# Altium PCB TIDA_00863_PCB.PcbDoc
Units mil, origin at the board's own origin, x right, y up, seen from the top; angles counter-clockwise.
Board outline 3000 x 2000 mil, 4 copper layers (Top Layer, Signal Layer 1, Signal Layer 2, Bottom Layer), stack 61.6 mil thick; 36 components, 14 nets, 116 pads, 117 vias.
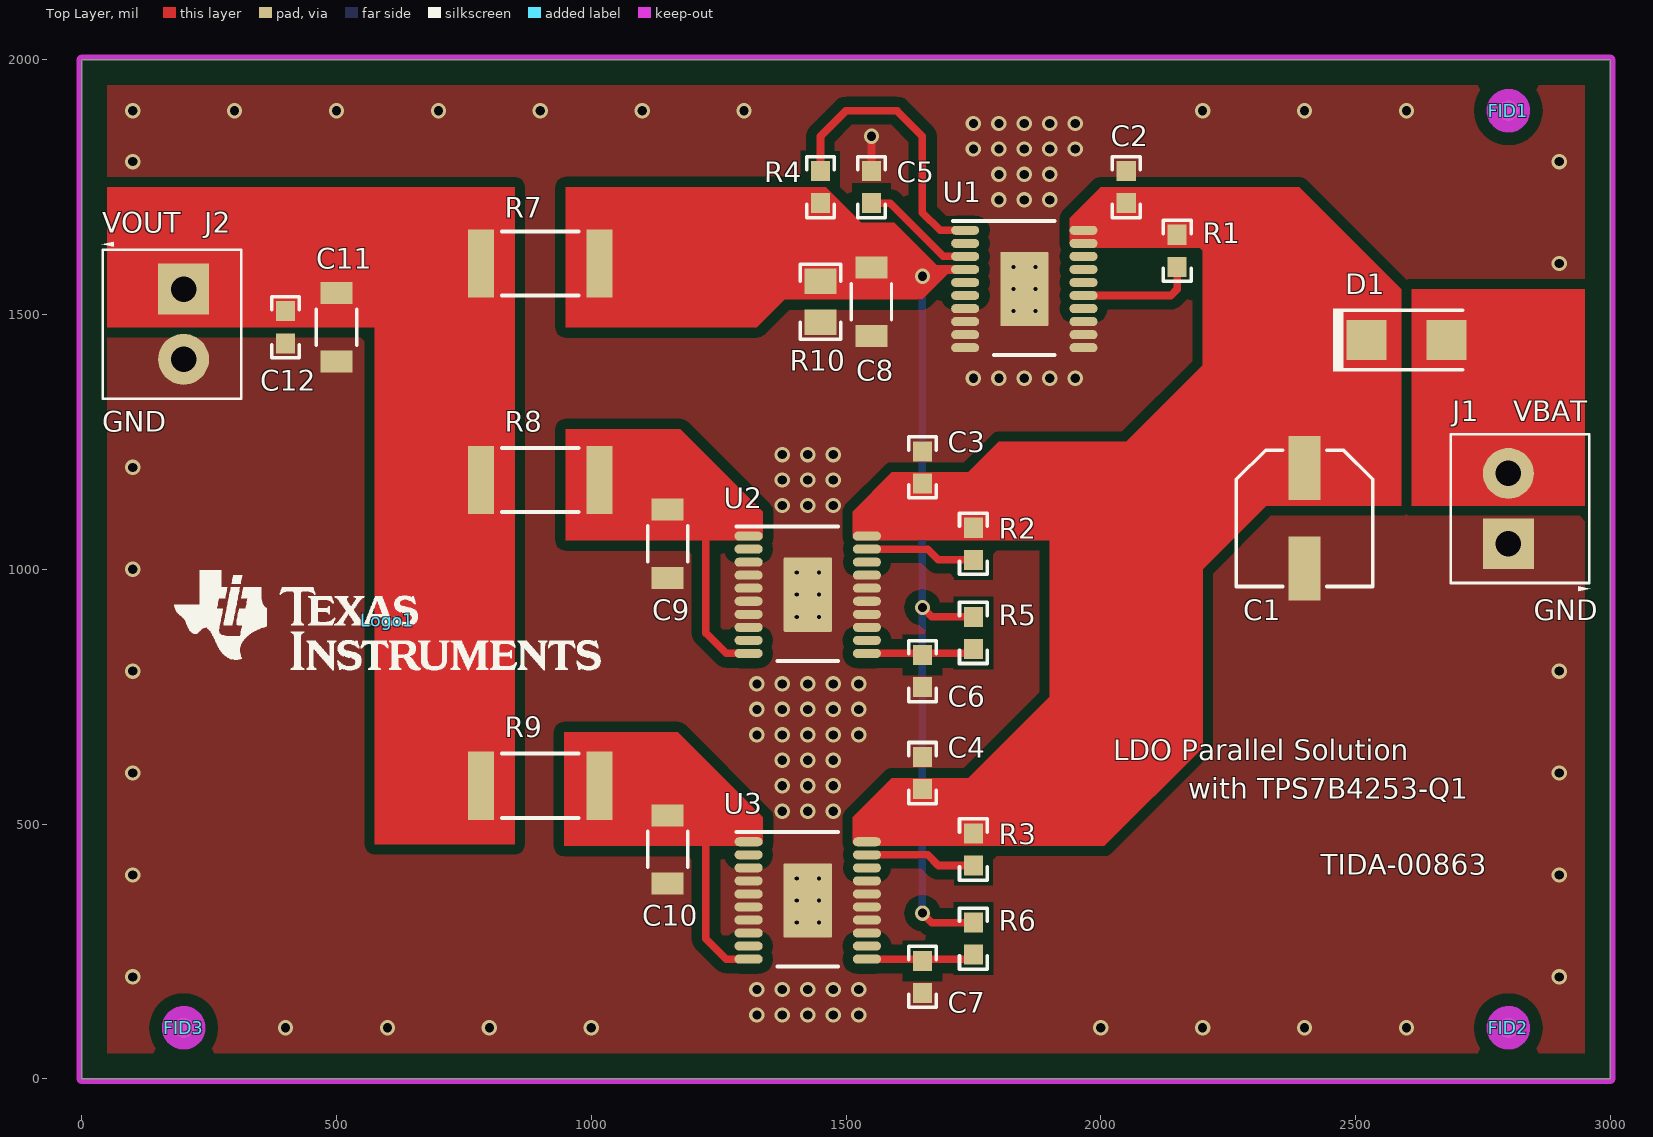
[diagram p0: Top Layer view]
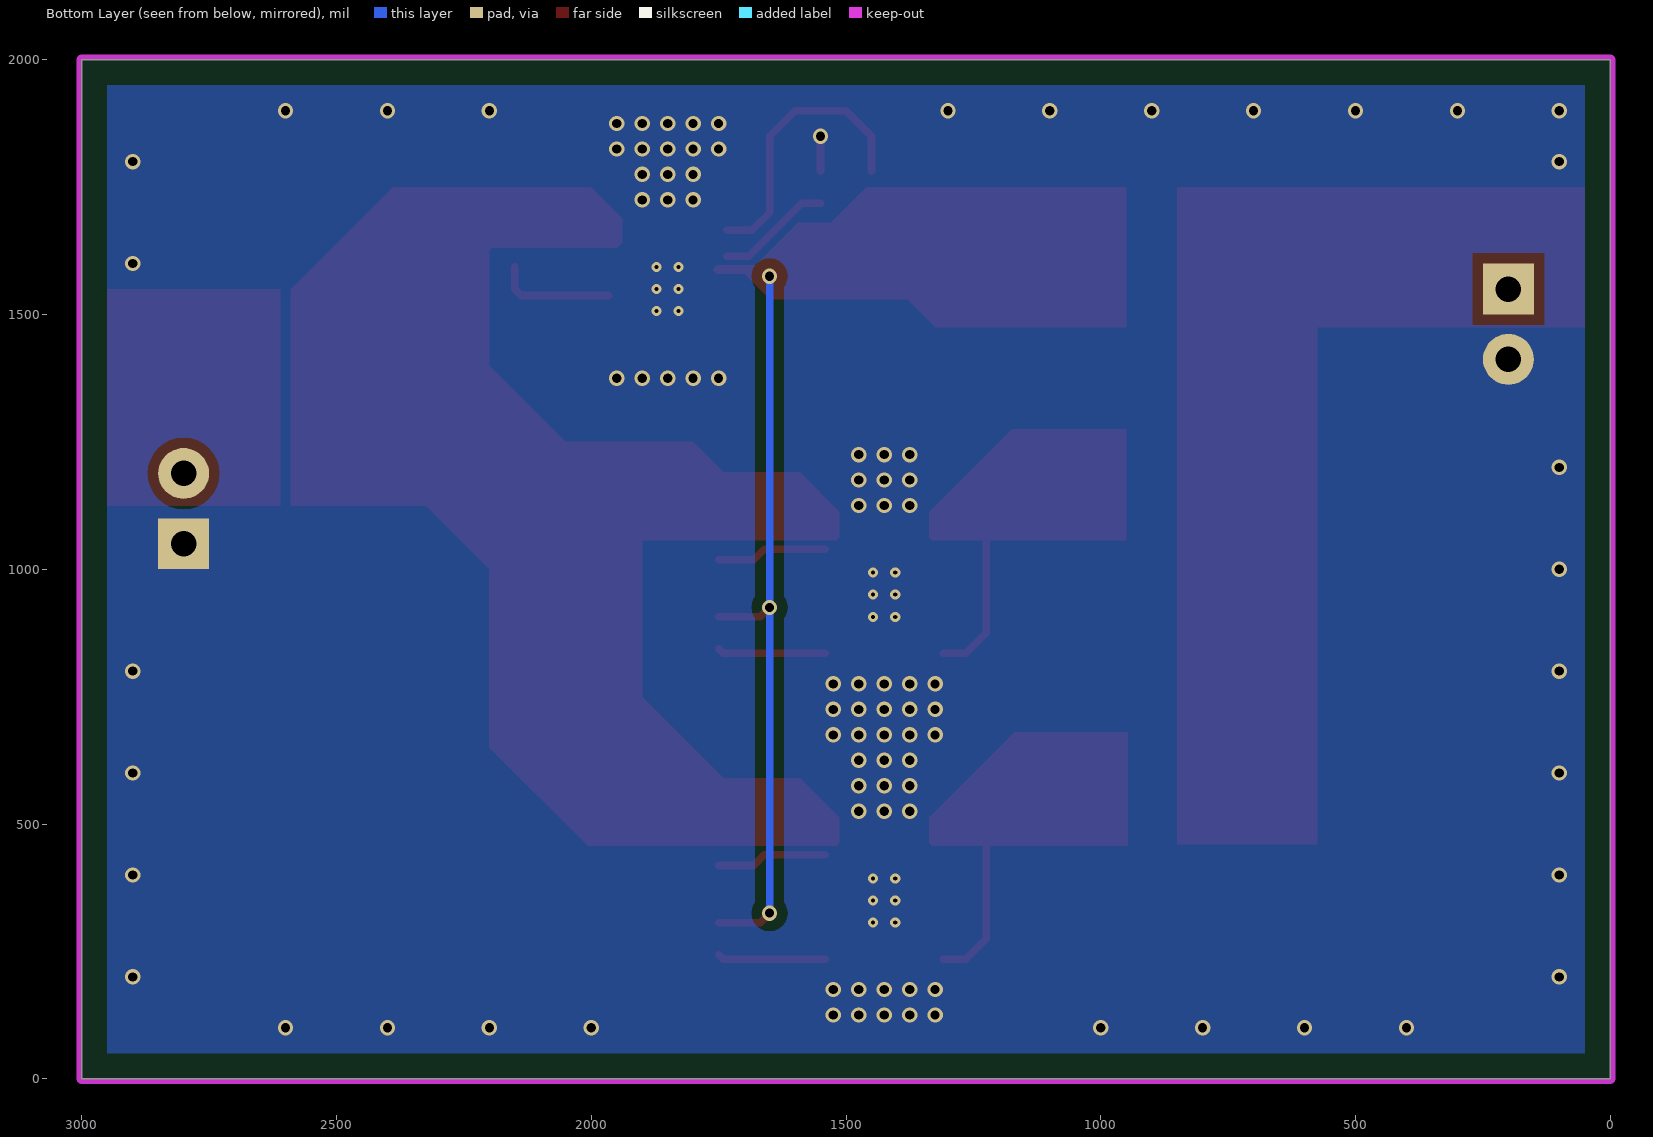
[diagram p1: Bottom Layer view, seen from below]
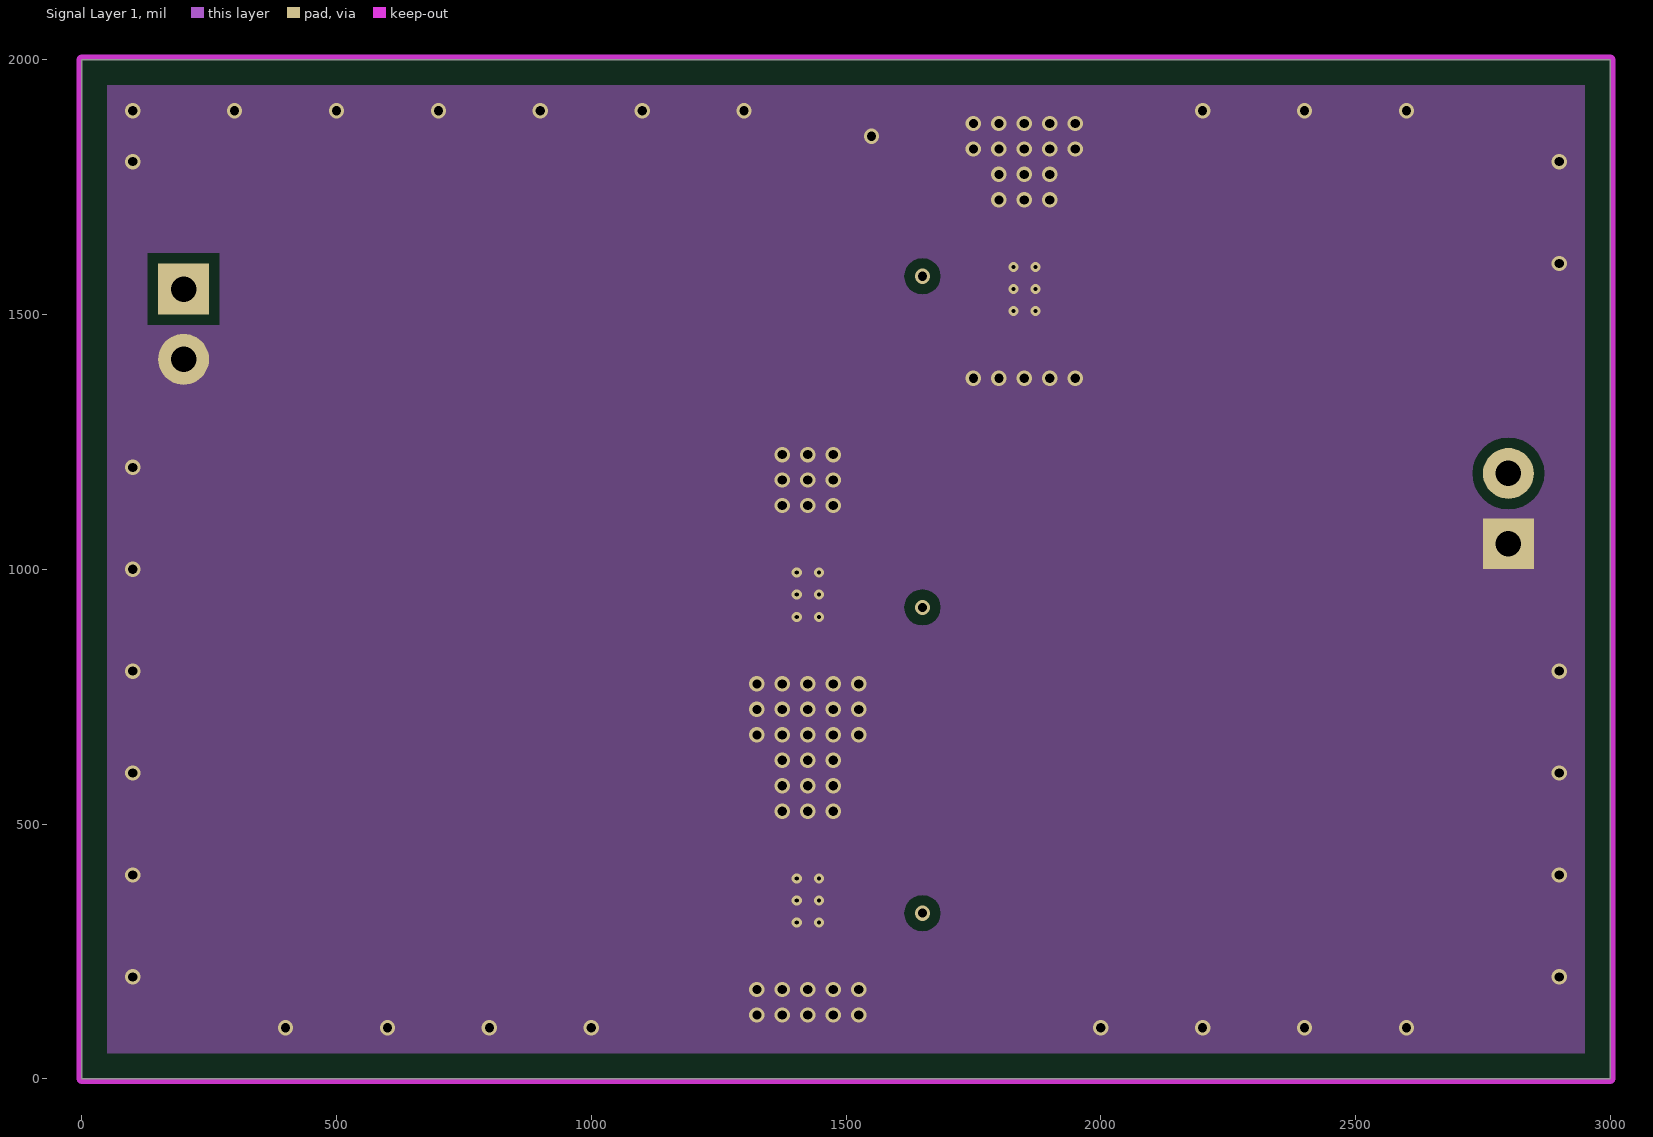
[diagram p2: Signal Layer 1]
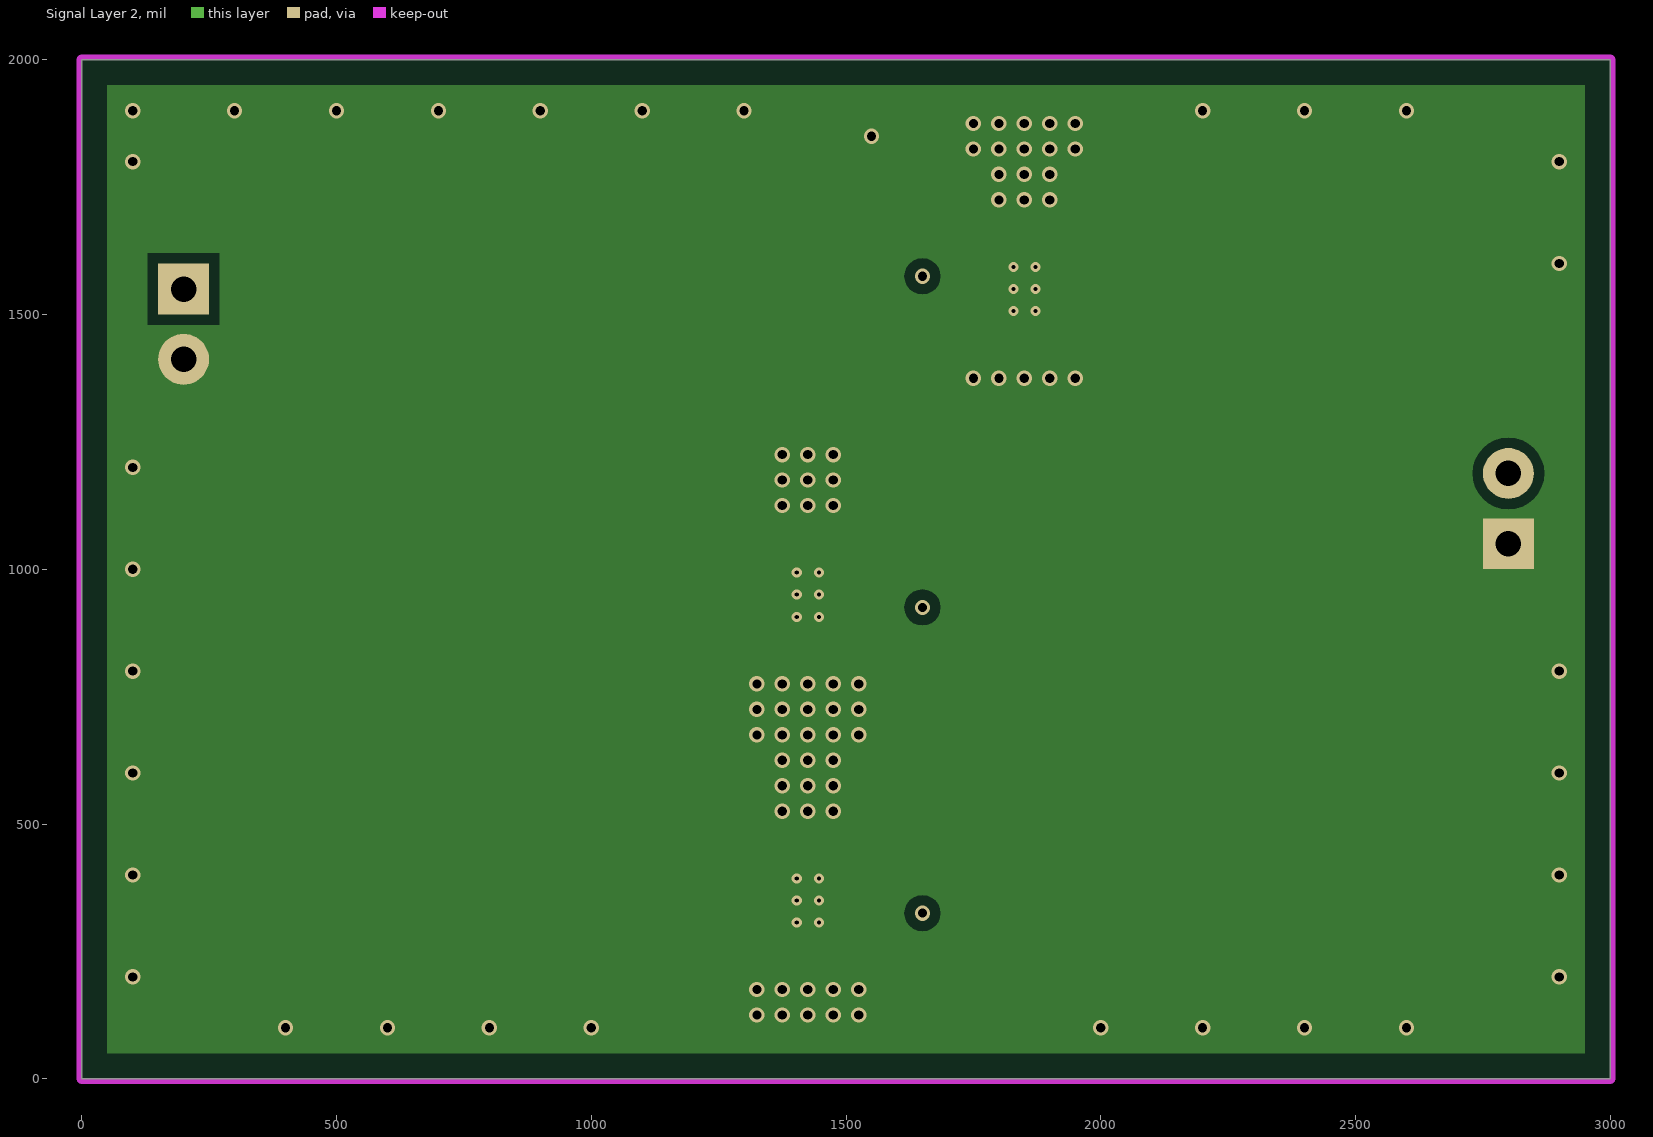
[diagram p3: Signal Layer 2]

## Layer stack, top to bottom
Top Solder: solder mask 0.4, Solder Resist, Dk 3.5
Top Layer: signal copper 1.4
Dielectric 1: core 8, Dk 4.2
Signal Layer 1: signal copper 1.4
Dielectric 2: prepreg 40, FR-4, Dk 4.2
Signal Layer 2: signal copper 1.4
Dielectric 3: core 8, Dk 4.2
Bottom Layer: signal copper 1.4
Bottom Solder: solder mask 0.4, Solder Resist, Dk 3.5

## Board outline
0,0 3000,0 3000,2000 0,2000

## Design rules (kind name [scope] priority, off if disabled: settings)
AcuteAngle [All] p1: minimum=4.50000000000000E+0001 checktracksonly=FALSE
AssemblyTestPointUsage [All] p1: valid=2
Clearance Clearance_Keepouts [((IsTrack Or IsArc) And Not InPoly) And IsFree and IsKeepOut vs ((IsTrack Or IsArc) And Not InPoly) And IsFree and IsKeepOut] p1: gap=0
Clearance Clearance_BoardEdge_MountingHoles [OnCopper and InComponentClass('Mounting Holes') vs IsKeepOut] p2: gap=40
Clearance Clearance_BoardEdge_Poly [OnCopper and InPoly vs IsKeepOut] p3: gap=25
Clearance Clearance_BoardEdge [OnCopper and Not InComponentClass('Logo') and not InComponentClass('FiducialMark') and not InRegion(1000,500,4000,800) and Not IsKeepout vs IsKeepOut] p4: gap=50
Clearance Clearance_Poly [InPolygon] p5: gap=20
Clearance [All] p6: gap=7.87
ComponentClearance ComponentClearance_MountingHoles_FiducialMarks [InComponentClass('Mounting Holes') vs InComponentClass('FiducialMark')] p1: gap=50 collisioncheckmode=3 verticalgap=10 showdistances=FALSE
ComponentClearance ComponentClearance_Shunt [InComponentClass('Header') vs InComponentClass('Shunt')] p2: gap=0 collisioncheckmode=3 verticalgap=0 showdistances=FALSE
ComponentClearance ComponentClearance_Logo [InComponentClass('Logo')] p3: gap=50 collisioncheckmode=3 verticalgap=10 showdistances=FALSE
ComponentClearance ComponentClearance_ScrewToNut [(HasFootprint('NY PMS 440 0025 PH')) vs (HasFootprint('Keystone_1902C'))] p4: gap=5 collisioncheckmode=3 verticalgap=10 showdistances=FALSE
ComponentClearance ComponentClearance_MountingHoles [InComponentClass('Mounting Holes')] p5: gap=100 collisioncheckmode=3 verticalgap=100 showdistances=FALSE
ComponentClearance ComponentClearance_SmallPassives [HasFootprint('0201*') or HasFootprint('0402*') or HasFootprint('0508') or HasFootprint('0603*') or HasFootprint('0612') or HasFootprint('0805*') or HasFootprint('0815*') or HasFootprint('0830*') or HasFootprint('1206*') or HasFootprint('1210*') or HasFootprint('1808*') or HasFootprint('1812*') or HasFootprint('1825*') or HasFootprint('2010*') or HasFootprint('2220*') or HasFootprint('2225*') or HasFootprint('2512*') or HasFootprint('2728*') or HasFootprint('3518*') vs HasFootprint('0201*') or HasFootprint('0402*') or HasFootprint('0508') or HasFootprint('0603*') or HasFootprint('0612') or HasFootprint('0805*') or HasFootprint('0815*') or HasFootprint('0830*') or HasFootprint('1206*') or HasFootprint('1210*') or HasFootprint('1808*') or HasFootprint('1812*') or HasFootprint('1825*') or HasFootprint('2010*') or HasFootprint('2220*') or HasFootprint('2225*') or HasFootprint('2512*') or HasFootprint('2728*') or HasFootprint('3518*')] p6: gap=20 collisioncheckmode=3 verticalgap=10 showdistances=FALSE
ComponentClearance ComponentClearance_THtoSMT [IsThruComponent vs IsSMTComponent] p7: gap=24.9 collisioncheckmode=3 verticalgap=30 showdistances=FALSE
ComponentClearance ComponentClearance_THtoTH [IsThruComponent vs IsThruComponent] p8: gap=24.9 collisioncheckmode=3 verticalgap=30 showdistances=FALSE
ComponentClearance [All] p9: gap=40 collisioncheckmode=3 verticalgap=10 showdistances=FALSE
DiffPairsRouting [All] p1: maxlimit=100 minlimit=10 mostfreqgap=10 toplayer_minwidth=15 toplayer_maxwidth=15 toplayer_prefwidth=15 midlayer1_minwidth=15 midlayer1_maxwidth=15 midlayer1_prefwidth=15 midlayer2_minwidth=15 midlayer2_maxwidth=15 midlayer2_prefwidth=15 bottomlayer_minwidth=15 bottomlayer_maxwidth=15 bottomlayer_prefwidth=15 maxuncoupledlength=1000
FabricationTestPointUsage TestPointUsage [All] p1: valid=2 allowmultiple=FALSE
FabricationTestpoint Testpoint [All] p1: side=3 testpointundercomponent=TRUE minsize=40 maxsize=100 preferedsize=60 minholesize=0 maxholesize=40 preferedholesize=32 testpointgrid=1 allowsidetop=TRUE allowsidebottom=TRUE usegrid=TRUE gridtolerance=0.01
FanoutControl Fanout_LCC [IsLCC] p1: bgadir=Out bgaviamode=Centered fanoutstyle=Auto fanoutdirection=Alternating viagrid=1 // Fanout_LCC (Default Rule)
FanoutControl Fanout_BGA [IsBGA] p2: bgadir=Out bgaviamode=Centered fanoutstyle=Auto fanoutdirection=Alternating viagrid=1 // Fanout_BGA (Default Rule)
FanoutControl Fanout_Default [All] p4: bgadir=Out bgaviamode=Centered fanoutstyle=Auto fanoutdirection=Alternating viagrid=1 // Fanout_Default (Default Rule)
FanoutControl Fanout_Small [(CompPinCount < 5)] p5: bgadir=Out bgaviamode=Centered fanoutstyle=Auto fanoutdirection=OutThenIn viagrid=1 // Fanout_Small (Default Rule)
HoleSize [All] p1: absolutevalues=TRUE maxlimit=251 minlimit=6 maxpercent=80.000 minpercent=20.000
MinimumAnnularRing MinimumAnnularRing_ThermalPadVias [IsVia and InAnyComponent] p1: minimumring=5.91
MinimumAnnularRing [All] p2: minimumring=6
MinimumSolderMaskSliver MinimumSolderMaskSliver_Logo [InComponentClass('Logo') vs InComponentClass('Logo')] p1: minsoldermaskwidth=0.7
MinimumSolderMaskSliver [All] p2: minsoldermaskwidth=3.94
PlaneConnect [All] p1: planeconnectstyle=Direct reliefexpansion=10 reliefentries=4 reliefconductorwidth=10 reliefairgap=10
PolygonConnect [All] p1: connectstyle=Direct reliefconductorwidth=10 reliefentries=4 polygonreliefangle="90 Angle" airgapwidth=10
RoutingVias ThermalPadVias [IsVia and InAnyComponent] p1: holewidth=7.87 width=19.68 viastyle="Through Hole" minholewidth=7.87 minwidth=19.68 maxholewidth=12.99 maxwidth=23.62
RoutingVias [All] p2: holewidth=16 width=34 viastyle="Through Hole" minholewidth=7.87 minwidth=26 maxholewidth=40 maxwidth=65
SilkToBoardRegionClearance [Not ((IsComment or IsDesignator) And (Hide <> 'False')) and not InRegion(1000,500,4000,800)] p1:
SilkToSilkClearance SilkToSilkClearance_Pb-FreeLogo [(HasFootprint('Pb-Free_Overlay_Medium') OR HasFootprint('Pb-Free_Overlay_Small')) vs (HasFootprint('Pb-Free_Overlay_Medium') OR HasFootprint('Pb-Free_Overlay_Small'))] p1: silktosilkclearance=0
SilkToSilkClearance [All] p2: silktosilkclearance=5
SilkToSolderMaskClearance "Silk to Solder Mask Opening" [All] p1: minsilkscreentomaskgap=1 clearancetoexposedcopper=FALSE
SolderMaskExpansion [All] p1: expansion=1.97
UnpouredPolygon [All] p1: allowunpoured=FALSE
Width [All] p1: maxlimit=100 minlimit=6 preferedwidth=10 checkconnectedcopper=TRUE
14 further rules are at their usual default settings.

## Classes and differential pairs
component class TPS7B4253_Parallel_Application_SCH: C1 C2 C3 C4 C5 C6 C7 C8 C9 C10 C11 C12 D1 J1 J2 R1 R2 R3 R4 R5 R6 R7 R8 R9 R10 U1 U2 U3
component class AssemblyNote: ZZ1 ZZ2 ZZ3 ZZ4
component class FiducialMark: FID1 FID2 FID3
component class TPS7B4253_Parallel_Application_Hardware: FID1 FID2 FID3 Logo1 ZZ1 ZZ2 ZZ3 ZZ4
component class Logo: Logo1

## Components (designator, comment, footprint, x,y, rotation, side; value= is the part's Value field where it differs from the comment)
C1 "EEE-FK1H220P" SM_RADIAL_D 2400,1100 r270 top
C2 "GCM188R71H104KA57D" 0603 2050,1750 r90 top
C3 "GCM188R71H104KA57D" 0603 1650,1200 r90 top
C4 "GCM188R71H104KA57D" 0603 1650,600 r90 top
C5 "GCM188R71H104KA57D" 0603 1550,1750 r270 top
C6 "GCM188R71H104KA57D" 0603 1650,800 r270 top
C7 "GCM188R71H104KA57D" 0603 1650,200 r270 top
C8 "GCM31CR71C106KA64L" 1206_190 1550,1525 r270 top
C9 "GCM31CR71C106KA64L" 1206_190 1150,1050 r270 top
C10 "GCM31CR71C106KA64L" 1206_190 1150,450 r270 top
C11 "GCM31CR71C106KA64L" 1206_190 500,1475 r270 top
C12 "GCM188R71H104KA57D" 0603 400,1475 r270 top
D1 "B260A-13-F" SMA 2600,1450 r0 top
FID1 "Fiducial" Fiducial10-20 2800,1900 r0 top
FID2 "Fiducial" Fiducial10-20 2800,100 r0 top
FID3 "Fiducial" Fiducial10-20 200,100 r0 top
J1 "ED555/2DS" TERM_BLK_ED555-2DS 2800,1050 r90 top
J2 "ED555/2DS" TERM_BLK_ED555-2DS 200,1550 r270 top
Logo1 "Texas Instruments" TI_Stacked_Overlay_Small 600,900 r0 top
R1 "CRCW060310K0FKEA" 0603 2150,1625 r90 top
R2 "CRCW060310K0FKEA" 0603 1750,1050 r90 top
R3 "CRCW060310K0FKEA" 0603 1750,450 r90 top
R4 "CRCW060310K0FKEA" 0603 1450,1750 r270 top
R5 "CRCW060310K0FKEA" 0603 1750,875 r90 top
R6 "CRCW060310K0FKEA" 0603 1750,275 r90 top
R7 "WSL2512R2000FEA" 2512 900,1600 r180 top
R8 "WSL2512R2000FEA" 2512 900,1175 r0 top
R9 "WSL2512R2000FEA" 2512 900,575 r0 top
R10 "CRCW0805365RFKEA" 0805_HV 1450,1525 r90 top
U1 "TPS7B6750QPWPRQ1" PWP0020D_N 1850,1550 r0 top
U2 "TPS7B4253QPWPRQ1" PWP0020D_N 1425,950 r0 top
U3 "TPS7B4253QPWPRQ1" PWP0020D_N 1425,350 r0 top
ZZ1 "This Assembly Note is for PCB labels only" AssemblyNoteLabel 185,3938 r0 top
ZZ2 "These assemblies are ESD sensitive, ESD precautions shall be observed." AssemblyNote 185,3829.11 r0 top
ZZ3 "These assemblies must be clean and free from flux and all contaminants. Use of no clean flux is not acceptable." AssemblyNote 185,3740.56 r0 top
ZZ4 "These assemblies must comply with workmanship standards IPC-A-610 Class 2, unless otherwise specified." AssemblyNote 185,3652 r0 top

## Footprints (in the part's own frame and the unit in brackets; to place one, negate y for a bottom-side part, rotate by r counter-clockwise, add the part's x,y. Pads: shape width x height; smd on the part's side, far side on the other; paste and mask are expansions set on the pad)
0603 [mm] "0603 from SM-752 data"
  rect 1x0.95 smd: 1(-0.8,0) 2(0.8,0)
  silkscreen extent -1.52,-0.69 1.52,0.69, body extent -0.87,-0.47 0.87,0.47, height 1
0805_HV [mil] "0805 with 30mil clearance between pads"
  rect 50x63 smd: 1(-40,0) 2(40,0)
  silkscreen extent -74,-40 74,40, body extent -43,-29 43,29, height 57
1206_190 [mm] "1206_190"
  rect 1.1x1.6 smd: 1(-1.7,0) 2(1.7,0)
  silkscreen extent -0.9,-1 0.9,1, body extent -1.75,-0.95 1.75,0.95, height 1.9
2512 [mm] "Chip Resistor, Body 6.3x3.2mm, IPC Medium Density"
  rect 1.3x3.4 smd: 1(-2.95,0) 2(2.95,0)
  silkscreen extent -1.9,-1.6 1.9,1.6, body extent -3.22,-1.67 3.22,1.67, height 0.71
AssemblyNote [mil] "Assembly Note"
AssemblyNoteLabel [mil] "Assembly Note for PCB Labels"
Fiducial10-20 [mm]
  round 1 smd mask+0.5: 1(0,0)
  Top Layer keep-out circle w1.178: c0,0 r0.5
PWP0020D_N [mm] "SOP, 20-Leads, Body 6.4x4.4mm, Pitch 0.65mm, Thermal Pad 2x3mm, IPC Medium Density"
  rrect100% 1.4x0.45 smd: 1(-2.95,2.925) 2(-2.95,2.275) 3(-2.95,1.625) 4(-2.95,0.975) 5(-2.95,0.325) 6(-2.95,-0.325) 7(-2.95,-0.975) 8(-2.95,-1.625) 9(-2.95,-2.275) 10(-2.95,-2.925) 11(2.95,-2.925) 12(2.95,-2.275) 13(2.95,-1.625) 14(2.95,-0.975) 15(2.95,-0.325) 16(2.95,0.325) 17(2.95,0.975) 18(2.95,1.625) 19(2.95,2.275) 20(2.95,2.925)
  rrect4% 2.4x3.7 smd: 21(0,0)
  silkscreen extent -3.55,-3.3 1.5,3.4, body extent -3.21,-3.25 3.21,3.25, height 1
SM_RADIAL_D [mm] "6.3 x 5.8mm:  Panasonic D"
  rect 3.2x1.6 smd: 1(-2.5,0) 2(2.5,0)
  silkscreen extent -3.4,-3.4 3.4,3.4, body extent -3.41,-3.41 3.41,3.41, height 6.1
SMA [mm] "Molded Diode, 2-Leads, Body 4.3x2.6mm, IPC Medium Density, based on OnSemi component dimensions and land pattern"
  rect 2x2 smd: 1(-2,0) 2(2,0)
  silkscreen extent -3.66,-1.57 2.79,1.57, body extent -2.6,-1.3 2.6,1.3, height 2.42
TERM_BLK_ED555-2DS [mil]
  rect 100x100 hole 50: 1(0,0)
  round 100 hole 50: 2(138,0)
  silkscreen extent -93,-161 215,113, body extent -69,-150 207,106, height 323
TI_Stacked_Overlay_Small [mil]
  silkscreen extent -418,-98 418,98

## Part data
C1: "CAP, AL, 22 µF, 50 V, +/- 20%, 0.88 ohm, SMD"
C2 C3 C4 C5 C6 C7 C12: "CAP, CERM, 0.1 µF, 50 V, +/- 10%, X7R, 0603"
C8 C9 C10 C11: "CAP, CERM, 10 µF, 16 V, +/- 10%, X7R, AEC-Q200 Grade 1, 1206_190"
D1: "Diode, Schottky, 60 V, 2 A, SMA"
FID1 FID2 FID3: "Fiducial mark.  There is nothing to buy or mount."
J1 J2: "Terminal Block, 6A, 3.5mm Pitch, 2-Pos, TH"
Logo1: library part TI_Logo, "Texas Instrument Corporate Signature"
R1 R2 R3 R4 R5 R6: "RES, 10.0 k, 1%, 0.1 W, 0603"
R7 R8 R9: "RES, 0.2, 1%, 1 W, 2512"
R10: "RES, 365, 1%, 0.125 W, 0805"
U1: "450-mA High-Voltage Ultra-Low IQ Low-Dropout Regulator, PWP0020D"
U2 U3: "300mA Low Dropout Voltage Tracking LDO, PWP0020D"
ZZ1: library part AssemblyNoteLabel
ZZ2 ZZ3 ZZ4: library part AssemblyNote

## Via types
v1: diameter 30, hole 18, Top Layer to Bottom Layer, 99 vias
v2: diameter 19.68, hole 7.87, Top Layer to Bottom Layer, 18 vias

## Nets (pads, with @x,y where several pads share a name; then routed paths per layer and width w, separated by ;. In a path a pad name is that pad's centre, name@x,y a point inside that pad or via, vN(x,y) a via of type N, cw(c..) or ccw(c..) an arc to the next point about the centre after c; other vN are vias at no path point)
ADJ_U2: C6.1 R5.1 U2.11 | length 212.4
  Top Layer w15: U2.11 1741.34,834.84 R5.1
ADJ_U3: C7.1 R6.1 U3.11 | length 212.4
  Top Layer w15: U3.11 1741.34,234.84 R6.1
GND: C1.2 C2.2 C3.2 C4.2 C5.1 C6.2 C7.2 C8.2 C9.2 C10.2 C11.2 C12.2 J1.1 J2.2 R10.1 U1.7 U1.8 U1.9 U1.10 U1.11 U1.12 U1.13 U1.21 U2.3 U2.4 U2.5 U2.6 U2.7 U2.8 U2.13 U2.14 U2.15 U2.16 U2.17 U2.21 U3.3 U3.4 U3.5 U3.6 U3.7 U3.8 U3.13 U3.14 U3.15 U3.16 U3.17 U3.21 | length 68.5
  Top Layer w15: C5.1 v1(1550,1850)
  other v1: 400,100 600,100 800,100 1000,100 2000,100 2200,100 2400,100 2600,100 1325,125 1375,125 1425,125 1475,125 1525,125 1325,175 1375,175 1425,175 1475,175 1525,175 100,200 2900,200 100,400 2900,400 1375,525 1425,525 1475,525 1375,575 1425,575 1475,575 100,600 2900,600 1375,625 1425,625 1475,625 1325,675 1375,675 1425,675 1475,675 1525,675 1325,725 1375,725 1425,725 1475,725 1525,725 1325,775 1375,775 1425,775 1475,775 1525,775 100,800 2900,800 100,1000 1375,1125 1425,1125 1475,1125 1375,1175 1425,1175 1475,1175 100,1200 1375,1225 1425,1225 1475,1225 1750,1375 1800,1375 1850,1375 1900,1375 1950,1375 2900,1600 1800,1725 1850,1725 1900,1725 1800,1775 1850,1775 1900,1775 100,1800 2900,1800 1750,1825 1800,1825 1850,1825 1900,1825 1950,1825 1750,1875 1800,1875 1850,1875 1900,1875 1950,1875 100,1900 300,1900 500,1900 700,1900 900,1900 1100,1900 1300,1900 2200,1900 2400,1900 2600,1900
  other v2: 1403.35,306.69 1446.65,306.69 1403.35,350 1446.65,350 1403.35,393.31 1446.65,393.31 1403.35,906.69 1446.65,906.69 1403.35,950 1446.65,950 1403.35,993.31 1446.65,993.31 1828.35,1506.69 1871.65,1506.69 1828.35,1550 1871.65,1550 1828.35,1593.31 1871.65,1593.31
NetC5_2: C5.2 U1.3 | length 227.2
  Top Layer w15: C5.2 1586.5,1718.5 1691.02,1613.98 U1.3
NetR1_1: R1.1 U1.15 | length 232.7
  Top Layer w15: U1.15 2137.2,1537.2 2150,1550 R1.1
NetR2_1: R2.1 U2.19 | length 217.6
  Top Layer w15: U2.19 1660.43,1039.57 1681.5,1018.5 R2.1
NetR3_1: R3.1 U3.19 | length 217.6
  Top Layer w15: U3.19 1660.43,439.57 1681.5,418.5 R3.1
NetR4_1: R4.1 U1.1 | length 558.2
  Top Layer w15: R4.1 1450,1850 1500,1900 1600,1900 1650,1850 1650,1700 1684.84,1665.16 U1.1
VBAT: D1.2 J1.2
VIN: C1.1 C2.1 C3.1 C4.1 D1.1 R1.2 R2.2 R3.2 U1.19 U1.20 U2.20 U3.20
VOUT: C11.1 C12.1 J2.1 R7.2 R8.1 R9.1
VOUT1: C8.1 R4.2 R5.2 R6.2 R7.1 R10.2 U1.4 | length 1465.3
  Top Layer w15: v1(1650,325) 1668.5,306.5 R6.2 ; v1(1650.04,924.96) 1668.5,906.5 R5.2
  Bottom Layer w15: v1(1650,325) v1(1650,1575)
VOUT2: C9.1 R8.2 U2.1 U2.10 | length 407.5
  Top Layer w15: C9.1 1208.07,1116.93 1225,1100 1225,875 1265.16,834.84 U2.10
VOUT3: C10.1 R9.2 U3.1 U3.10 | length 407.5
  Top Layer w15: C10.1 1208.07,516.93 1225,500 1225,275 1265.16,234.84 U3.10
pads on no net: FID1.1 FID2.1 FID3.1 U1.2 U1.5 U1.6 U1.14 U1.16 U1.17 U1.18 U2.2 U2.9 U2.12 U2.18 U3.2 U3.9 U3.12 U3.18

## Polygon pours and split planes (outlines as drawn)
GND on Bottom Layer "Bottom Layer-GND" (solid, remove dead copper, pour order 5): 50,1950 50,50 2950,50 2950,1950
GND on Top Layer "Top Layer-GND" (solid, remove dead copper, pour order 7): 50,1950 50,50 2950,50 2950,1950
GND on Signal Layer 1 "Signal Layer 1-GND" (solid, remove dead copper, pour order 6): 50,50 2950,50 2950,1950 50,1950
GND on Signal Layer 2 "Signal Layer 2-GND" (solid, remove dead copper, pour order 8): 50,50 2950,50 2950,1950 50,1950

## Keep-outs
Keep-Out Layer:
  lines w10: -5,0 ccw(c0,0) 0,-5 ; -5,0 ccw(c0,0) 0,-5 ; -5,0 -5,2000 ; -5,2000 cw(c0,2000) 0,2005 ; -5,2000 cw(c0,2000) 0,2005 ; 0,-5 3000,-5 ; 0,2005 3000,2005 ; 3000,-5 ccw(c3000,0) 3005,0 ; 3000,-5 ccw(c3000,0) 3005,0 ; 3000,2005 cw(c3000,2000) 3005,2000 ; 3000,2005 cw(c3000,2000) 3005,2000 ; 3005,0 3005,2000
  text ".Layer_Name" at 577,-858.49 h60

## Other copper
Top Layer:
  region net VBAT: 2950,1550 2950,1125 2610,1125 2610,1550
  region net VOUT1: 1761,1590 1761,1586 1755,1580 1700,1580 1650,1530 1380,1530 1325,1475 950,1475 950,1720 950,1750 1460,1750 1530,1680 1595,1680 1678,1597 1754,1597
  region net VIN: 1513,1062 1513,1113 1590,1190 1740,1190 1800,1250 2050,1250 2407.32,1607.32 2407.32,1207.32 2200,1000 1900,1000 1900,1057 1518,1057
  region net VIN: 1513,462 1513,513 1590,590 1740,590 1850,700 2200,700 2200,650 2007,457 1518,457
  region net VOUT2: 1337,1062 1337,1113 1175,1275 950,1275 950,1057 1332,1057
  region net VOUT3: 1337,462 1337,513 1170,680 946.97,680 946.97,457 1332,457
  region net VOUT: 850,1750 850,1475 50,1475 50,1750
  region net VOUT: 850,460 575,460 575,1750 850,1750
  region net VIN: 2590,1498.91 2590,1550 2390,1750 2000,1750 1939,1689 1939,1641 1949,1631 2194,1631 2200,1625 2200,1498.91
  region net VIN: 2007,457 2200,650 2200,1125 1900,1125 1900,750 1850,700 1850,457
  region net VIN: 2590,1550 2200,1550 2200,1125 2590,1125
  text ".Layer_Name" at 577,-858.49 h60
Bottom Layer:
  text ".Layer_Name" at 577,-858.49 h60

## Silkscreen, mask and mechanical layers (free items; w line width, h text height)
Top Overlay:
  text "VOUT" at 40,1660 h40
  text "VBAT" at 2810,1290 h40
  text "GND" at 40,1270 h40
  text "GND" at 2850,900 h40
  text "LDO Parallel Solution" at 2024.98,625 h40
  text "with TPS7B4253-Q1" at 2171.59,550 h40
  text "TIDA-00863" at 2431.51,400 h40
  text ".Layer_Name" at 577,-858.49 h60
Bottom Overlay:
  text ".Layer_Name" at 577,-858.49 h60
Top Paste:
  text ".Layer_Name" at 577,-858.49 h60
Bottom Paste:
  text ".Layer_Name" at 577,-858.49 h60
Top Solder:
  text ".Layer_Name" at 577,-858.49 h60
  text ".Layer_Name" at 577,-858.49 h60
Bottom Solder:
  text ".Layer_Name" at 577,-858.49 h60
Drill Guide:
  text ".Layer_Name" at 577,-858.49 h60
M1 Board Outline:
  the board outline again, w10
  text ".Layer_Name" at 577,-858.49 h60
M2 Board Dimensions:
  rectangle: 125,-400 500,-275
  rectangle: 0,-275 125,-150
  lines w7: 0,-275 1000,-275 ; 125,-400 125,-150 ; 250,-400 250,-150 ; 500,-400 500,-150 ; 750,-400 750,-150 ; 0,-400 0,-150 1000,-150 1000,-400 0,-400
  text ".Layer_Name" at 577,-858.49 h60
M3 3D STEP Top:
  text ".Layer_Name" at 577,-858.49 h60
M4 3D STEP Bottom:
  text ".Layer_Name" at 577,-858.49 h60
M5 Assembly Top:
  lines w10: -292,-930.17 6308,-930.17 ; -292,-726.83 6310,-726.83 ; -292,-523.5 -292,-1133.5 3713,-1133.5 6310,-1133.5 6310,-523.5 -291.5,-523.5 -291.5,-1133.5 1284,-1133.5 ; 2173,-1133.5 2173,-523.5 ; 3440,-726.83 3440,-523.5 ; 4280,-726.83 4280,-523.5 ; 4902,-1140 4902,-937.17
  text "COMPONENTS MARKED 'DNP' SHOULD NOT BE POPULATED." at 1153.5,-318.5 h60
  text "ASSEMBLY VARIANT:" at 1153,-434 h60
  text ".VariantName" at 2189,-434 h60
  text "PCB VIEWED FROM TOP SIDE" at -228.5,-655.67 h60
  text "BOARD #:" at 2248,-655.67 h60
  text ".PRJ_Number" at 2793.5,-655.67 h60
  text "REV:" at 3638,-655.67 h60
  text ".PCB_Rev" at 3929.5,-655.67 h60
  text "SVN REV:" at 4476,-655.67 h60
  text ".VersionControl_RevNumber" at 4982,-655.67 h60
  text "PLOT NAME =" at -228.5,-1064.34 h60
  text ".plot_File_Name" at 577,-1064.34 h60
  text "GENERATED    :" at 2250,-1064.34 h60
  text ".Print_Date" at 3119.5,-1064.34 h60
  text ".Print_Time" at 3848.5,-1064.34 h60
  text "TEXAS INSTRUMENTS" at 5113,-1064.34 h60
M6 Assembly Bottom:
  lines w10: -292.5,-727.33 6309.5,-727.33 ; -290.5,-930.67 6309.5,-930.67 ; 1115.5,-1140.5 1115.5,-937.67 ; 1737.5,-727.33 1737.5,-524 ; 2577.5,-727.33 2577.5,-524 ; 3844.5,-1134 3844.5,-524 ; 4733.5,-1134 6309,-1134 6309,-524 -292.5,-524 -292.5,-1134 2304.5,-1134 6309.5,-1134 6309.5,-524
  text "COMPONENTS MARKED 'DNP' SHOULD NOT BE POPULATED." at 6102,-318 h60
  text ".VariantName" at 5058,-434 h60
  text "ASSEMBLY VARIANT:" at 6097,-434 h60
  text ".VersionControl_RevNumber" at 1035.5,-656.17 h60
  text "SVN REV:" at 1541.5,-656.17 h60
  text ".PCB_Rev" at 2088,-656.17 h60
  text "REV:" at 2379.5,-656.17 h60
  text ".PRJ_Number" at 3224,-656.17 h60
  text "BOARD #:" at 3769.5,-656.17 h60
  text "PCB VIEWED FROM BOTTOM SIDE" at 6246,-656.17 h60
  text "TEXAS INSTRUMENTS" at 904.5,-1064.84 h60
  text ".Print_Time" at 2169,-1064.84 h60
  text ".Print_Date" at 2898,-1064.84 h60
  text "GENERATED    :" at 3767.5,-1064.84 h60
  text ".plot_File_Name" at 5440.5,-1064.84 h60
  text "PLOT NAME =" at 6246,-1064.84 h60
M9 Title Sheet:
  drawing of 57 lines, arcs and shapes, not listed
  text "1" at 739.84,8036.5 h70
  text "2" at 3235.5,8036.5 h70
  text "3" at 5724.84,8036.5 h70
  text "4" at 8231.51,8036.5 h70
  text "5" at 10730.5,8036.5 h70
  text "6" at 13235.5,8036.5 h70
  text "A" at -416.5,6893.5 h70
  text "A" at 14383.5,6893.5 h70
  text "B" at -416.5,4513.5 h70
  text "B" at 14383.5,4513.5 h70
  text "C" at -416.5,2138.5 h70
  text "C" at 14383.5,2138.5 h70
  text "PROJECT TITLE:" at 11343.5,277.5 h45
  text ".PRJ_Title" at 11393.5,144.17 h70
  text "DESIGNED FOR:" at 11343.5,-23.5 h45
  text ".PRJ_Customer" at 11393.5,-163.5 h70
  text "D" at -416.5,-231.5 h70
  text "D" at 14383.5,-231.5 h70
  text "FILE NAME:" at 11343.5,-323.5 h45
  text ".PCB_File_Name_No_Path" at 11393.5,-443.5 h70
  text "Texas Instruments (TI) and/or its licensors do not warrant the accuracy or completeness of this specification" at 6374,-605.34 h45
  text "ENGINEER:" at 11343.5,-613.5 h45
  text "LAYOUT BY:" at 12848.5,-613.5 h45
  text "or any information contained therein. TI and/or its licensors do not warrant that this design will meet" at 6329.01,-718 h45
  text ".PRJ_Engineer" at 11393.5,-768.49 h70
  text ".PCB_Layout" at 12899,-768.49 h70
  text "the specifications, will be suitable for your application or fit for any particular purpose, or will operate in" at 6329.01,-830.67 h45
  text ".Layer_Name" at 577,-858.49 h60
  text "ALTIUM DESIGNER VERSION:" at 12848.5,-923.5 h45
  text "an implementation. TI and/or its licensors do not warrant that the design is production worthy. You should" at 6329.01,-943.33 h45
  text "completely validate and test your design implementation to confirm the system functionality for your application." at 6374,-1056 h45
  text ".print_Scale" at 11393.5,-1056.83 h70
  text ".Application_BuildNumber" at 12899,-1056.83 h70
  text "1" at 739.84,-1263.5 h70
  text "2" at 3235.5,-1263.5 h70
  text "3" at 5724.84,-1263.5 h70
  text "4" at 8231.51,-1263.5 h70
  text "5" at 10730.5,-1263.5 h70
  text "6" at 13235.5,-1263.5 h70
M10 Fab Notes:
  drawing of 185 lines, arcs and shapes, not listed
  text "DESIGN INFORMATION" at 12381.02,5910 h60
  text "MIN. TRACK WIDTH:" at 11736.46,5730 h60
  text "8" at 12832.7,5730 h60
  text "MIL" at 12987.46,5730 h60
  text "MIN. CLEARANCE:" at 11736.46,5598 h60
  text "0.2" at 12772.7,5598 h60
  text "mm" at 12987.46,5598 h60
  text "MIN. VIA PAD SIZE:" at 11736.46,5466 h60
  text "24" at 12802.71,5466 h60
  text "MIL" at 12987.46,5466 h60
  text "0.05mm (2MIL)" at 12431.46,5324.29 h60
  text "MINIMUM ANNULAR RING" at 11407.23,5320 h60
  text "EXTERNAL" at 13139.46,5320 h60
  text "PER" at 11607.23,5202 h60
  text "IPC-D-275 CLASS 2 LEVEL C" at 11827.23,5202 h60
  text "MIL, HOLES" at 13315.46,5089.71 h60
  text "+/-" at 12923,5089 h60
  text "+/-" at 13777,5089 h60
  text "REGISTRATION TOLERANCES:" at 11407.23,5084 h60
  text "METAL" at 12607,5084 h60
  text "5" at 13183.2,5084 h60
  text "3" at 14016.2,5084 h60
  text "MIL" at 14132.46,5084 h60
  text "MATERIAL:" at 11332.46,4874.54 h60
  text "FR-4 High Tg" at 12318.9,4734.21 h60
  text "FR-408" at 11753.46,4725.64 h60
  text "X" at 12165.46,4725.64 h60
  text "OTHER" at 13241.46,4725.64 h60
  text "62 MIL (1.6mm) +/-10%" at 12073.56,4562.92 h60
  text "THICKNESS:" at 11407.23,4558.64 h60
  text "X" at 11945.4,4558.64 h60
  text "OTHER" at 13358.46,4558.64 h60
  text "TOLERANCE:" at 11407.23,4400.64 h60
  text "X" at 12246.53,4400.64 h60
  text "ANSI IPC-6012 TYPE 3 CLASS 2" at 12433.48,4400.64 h60
  text "OTHER +/-" at 12433.46,4244.64 h60
  text "BOW & TWIST:" at 11407.23,4087.64 h60
  text "X" at 12246.53,4087.64 h60
  text "ANSI IPC-6012 TYPE 3 CLASS 2" at 12433.48,4087.64 h60
  text "OTHER +/-" at 12433.46,3929.13 h60
  text "DRILLING:" at 11332.46,3790.64 h60
  text "REFERENCE:" at 11407.23,3673.64 h60
  text "X" at 12055.46,3673.64 h60
  text "AS SHOWN" at 12242.46,3673.64 h60
  text "X" at 12956.46,3673.64 h60
  text "NC_DRILL FILES" at 13093.46,3673.64 h60
  text "PTH MIN COPPER THICKNESS:" at 11407.23,3515.64 h60
  text "X" at 12757.46,3515.64 h60
  text "1MIL" at 12894.46,3515.64 h60
  text "OTHER" at 13391.46,3515.64 h60
  text "BOARD FINISH:" at 11332.46,3356.64 h60
  text "SILKSCREEN:" at 11487.68,3238.64 h60
  text "X" at 12436.46,3238.64 h60
  text "TOP" at 12562.46,3238.64 h60
  text "BOTTOM" at 13073.46,3238.64 h60
  text "SILKSCREEN COLOR:" at 11487.68,3071.64 h60
  text "X" at 12435.42,3071.64 h60
  text "WHITE" at 12562.46,3071.64 h60
  text "OTHER" at 13073.46,3071.64 h60
  text "SOLDER RESIST COLOR:" at 11487.68,2901.64 h60
  text "GREEN" at 12182.46,2742.44 h60
  text "BLUE" at 12773.46,2742.44 h60
  text "OTHER" at 13311.46,2742.44 h60
  text "X" at 13160,2740 h60
  text "RED" at 13730,2740 h60
  text "IMMERSION GOLD (ENIG)" at 12393.46,2553.92 h60
  text "ENEPIG" at 13731,2550.64 h60
  text "SURFACE FINISH:" at 11332.46,2549.64 h60
  text "X" at 12206.51,2549.64 h60
  text "IMM. TIN/SILVER OR EQUIV" at 11662,2392.64 h60
  text "OTHER" at 13093.46,2392.64 h60
  text "ARRAY/PANEL:" at 11332.46,2213.64 h60
  text "CUT AND TRIM PER MECH LAYER 1" at 12393.46,2209.35 h60
  text "N.C. ROUTE" at 12393.46,2057.64 h60
  text "X" at 13072.46,2057.64 h60
  text "V. SCORE" at 13259.46,2057.64 h60
  text "CERTIFICATION:" at 11332.46,1920.64 h60
  text "MATERIALS AND WORKMANSHIP FOR ALL PCBS" at 12057.46,1920.64 h60
  text "TO MEET OR EXCEED THE REQUIREMENTS OF:" at 12057.46,1822.64 h60
  text "X" at 11683.96,1686.13 h60
  text "ANSI IPC-A-600F CLASS ->" at 11822.96,1686.13 h60
  text "X" at 13462.02,1686.13 h60
  text "2" at 13580.96,1686.14 h60
  text "1" at 13265.96,1684.64 h60
  text "3" at 13934.96,1684.64 h60
  text "X" at 11686.02,1526.64 h60
  text "UL 94V-0" at 11822.96,1526.64 h60
  text "X" at 12498.02,1526.64 h60
  text "RoHS" at 12634.96,1526.64 h60
  text "OTHER" at 13279.36,1526.64 h60
  text "PER ORDER" at 13676.42,1526.64 h60
  text "ADDITIONAL REQUIREMENTS:" at 11332.46,1385.64 h60
  text "MICROSECTION:" at 11407.23,1270.64 h60
  text "YES" at 12312.96,1270.64 h60
  text "REQUIRED" at 13174.46,1114.49 h60
  text "BARE BOARD ELEC. TEST:" at 11407.23,1111.64 h60
  text "NONE" at 12712.96,1111.64 h60
  text "X" at 13047.46,1111.64 h60
  text "PER ORDER" at 13766.46,1111.64 h60
  text "MANUFACTURER'S UL:" at 11407.23,954.64 h60
  text "RAIL" at 12572.96,950.35 h60
  text "METAL" at 13064.77,950.35 h60
  text "SILK" at 13576.46,950.35 h60
  text ".Layer_Name" at 577,-858.49 h60
M11 Gerber Information:
  lines w10: -292,-930.17 6308,-930.17 ; -292,-726.83 6310,-726.83 ; -292,-523.5 -292,-1133.5 3713,-1133.5 6310,-1133.5 6310,-523.5 -291.5,-523.5 -291.5,-1133.5 1284,-1133.5 ; 2173,-1133.5 2173,-523.5 ; 3440,-726.83 3440,-523.5 ; 4280,-726.83 4280,-523.5 ; 4902,-1140 4902,-937.17
  text "ALL ARTWORK VIEWED FROM TOP SIDE" at -228.5,-655.67 h60
  text "BOARD #:" at 2248,-655.67 h60
  text ".PRJ_Number" at 2793.5,-655.67 h60
  text "REV:" at 3638,-655.67 h60
  text ".PCB_Rev" at 3929.5,-655.67 h60
  text "SVN REV:" at 4476,-655.67 h60
  text ".VersionControl_RevNumber" at 4982,-655.67 h60
  text "LAYER NAME =" at -228.5,-858.49 h60
  text "PLOT NAME =" at -228.5,-1064.34 h60
  text ".plot_File_Name" at 577,-1064.34 h60
  text "GENERATED    :" at 2250,-1064.34 h60
  text ".Print_Date" at 3119.5,-1064.34 h60
  text ".Print_Time" at 3848.5,-1064.34 h60
  text "TEXAS INSTRUMENTS" at 5113,-1064.34 h60
M12 Stackup:
  drawing of 295 lines, arcs and shapes, not listed
  text "Layer" at 9750.58,7800 h60
  text "Name" at 10160.49,7800 h60
  text "Material" at 11100.23,7800 h60
  text "Thickness" at 11960,7800 h60
  text "Constant" at 12609.84,7800 h60
  text "Board Layer Stack" at 13179.7,7800 h60
  text "1" at 9750.58,7680 h60
  text "Top Overlay" at 10160.49,7680 h60
  text "2" at 9750.58,7560 h60
  text "Top Solder" at 10160.49,7560 h60
  text "Solder Resist" at 11100.23,7560 h60
  text "0.40mil" at 11960,7560 h60
  text "3.5" at 12609.84,7560 h60
  text "3" at 9750.58,7440 h60
  text "Top Layer" at 10160.49,7440 h60
  text "Copper" at 11100.23,7440 h60
  text "1.40mil" at 11960,7440 h60
  text "4" at 9750.58,7320 h60
  text "Dielectric 1" at 10160.49,7320 h60
  text "8.00mil" at 11960,7320 h60
  text "4.2" at 12609.84,7320 h60
  text "5" at 9750.58,7200 h60
  text "Signal Layer 1" at 10160.49,7200 h60
  text "Copper" at 11100.23,7200 h60
  text "1.40mil" at 11960,7200 h60
  text "6" at 9750.58,7080 h60
  text "Dielectric 2" at 10160.49,7080 h60
  text "FR-4" at 11100.23,7080 h60
  text "40.00mil" at 11960,7080 h60
  text "4.2" at 12609.84,7080 h60
  text "7" at 9750.58,6960 h60
  text "Signal Layer 2" at 10160.49,6960 h60
  text "Copper" at 11100.23,6960 h60
  text "1.40mil" at 11960,6960 h60
  text "8" at 9750.58,6840 h60
  text "Dielectric 3" at 10160.49,6840 h60
  text "8.00mil" at 11960,6840 h60
  text "4.2" at 12609.84,6840 h60
  text "9" at 9750.58,6720 h60
  text "Bottom Layer" at 10160.49,6720 h60
  text "Copper" at 11100.23,6720 h60
  text "1.40mil" at 11960,6720 h60
  text "10" at 9750.58,6600 h60
  text "Bottom Solder" at 10160.49,6600 h60
  text "Solder Resist" at 11100.23,6600 h60
  text "0.40mil" at 11960,6600 h60
  text "3.5" at 12609.84,6600 h60
  text "11" at 9750.58,6480 h60
  text "Bottom Overlay" at 10160.49,6480 h60
  text ".Layer_Name" at 577,-858.49 h60
M13 Component Bodies Top:
  text ".Layer_Name" at 577,-858.49 h60
M14 Component Bodies Bottom:
  text ".Layer_Name" at 577,-858.49 h60
M15 Courtyards Top:
  text ".Layer_Name" at 577,-858.49 h60
M16 Courtyards Bottom:
  text ".Layer_Name" at 577,-858.49 h60
Drill Drawing:
  circle w1: c4592.8,2270.83 r24.91
  lines w1: 4567.89,1959.46 4580.35,1959.46 4592.8,1947 4605.26,1959.46 4617.71,1959.46 4605.26,1971.91 4617.71,1984.37 4605.26,1984.37 4592.8,1996.82 4580.35,1984.37 4567.89,1984.37 4580.35,1971.91 4567.89,1959.46 ; 4567.89,2096.46 4592.8,2108.92 4617.71,2096.46 4605.26,2121.37 4617.71,2146.28 4592.8,2133.83 4567.89,2146.28 4580.35,2121.37 4567.89,2096.46
  lines w12: 4500,1902.17 6619.4,1902.17 ; 4500,2350.54 6619.4,2350.54 ; 4870.67,1752.71 4870.67,2500 ; 5227.78,1752.71 5227.78,2500 ; 5889.79,1752.71 5889.79,2500 ; 6174.14,1752.71 6174.14,2500 ; 4500,1752.71 6619.4,1752.71 6619.4,2500 4500,2500 4500,1752.71
  text "Symbol" at 4589.68,2395.38 h72
  text "Quantity" at 4915.51,2395.38 h72
  text "Finished Hole Size" at 5272.62,2395.38 h72
  text "Plated" at 5934.62,2395.38 h72
  text "Hole Type" at 6218.98,2395.38 h72
  text "18" at 4915.51,2245.92 h60
  text "7.87mil (0.200mm)" at 5272.62,2245.92 h60
  text "PTH" at 5934.62,2245.92 h60
  text "Round" at 6218.98,2245.92 h60
  text "99" at 4915.51,2096.46 h60
  text "18.00mil (0.457mm)" at 5272.62,2096.46 h60
  text "PTH" at 5934.62,2096.46 h60
  text "Round" at 6218.98,2096.46 h60
  text "4" at 4915.51,1947 h60
  text "50.00mil (1.270mm)" at 5272.62,1947 h60
  text "PTH" at 5934.62,1947 h60
  text "Round" at 6218.98,1947 h60
  text "121 Total" at 4915.51,1797.54 h60
  text ".Layer_Name" at 577,-858.49 h60

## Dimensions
0,0 to 3000,0 on M2 Board Dimensions
0,0 to 0,2000 on M2 Board Dimensions
0,-400 to 1000,-400 on M2 Board Dimensions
